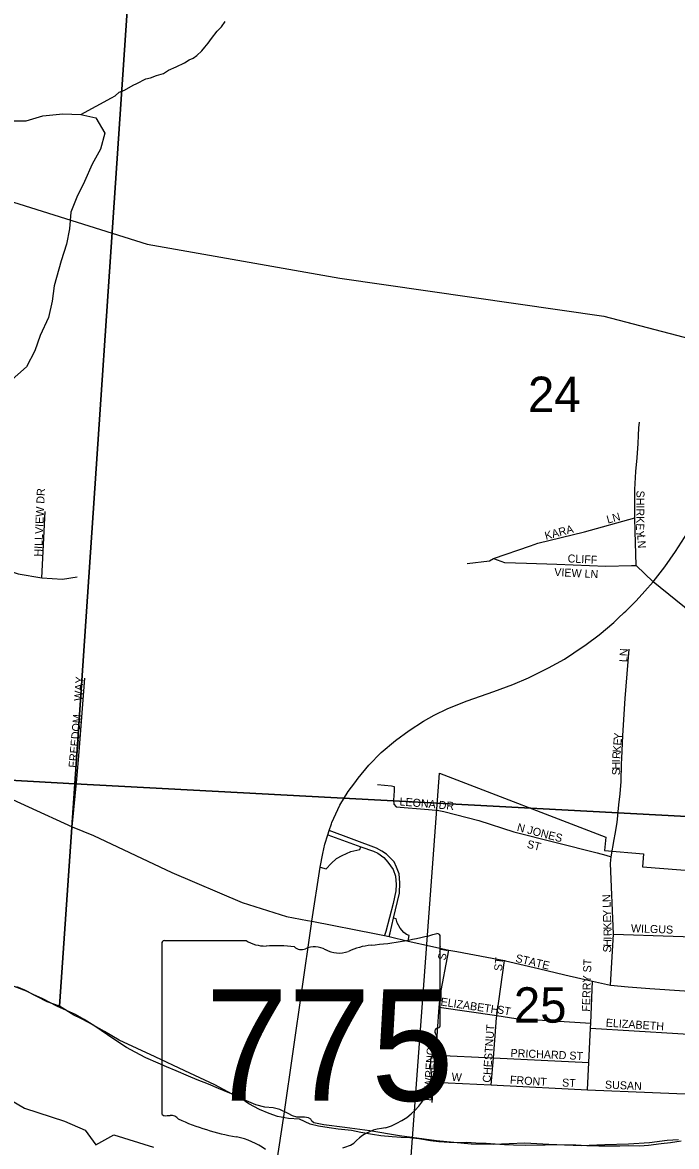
# Model space of a CAD drawing. Extents: x 0 to 34, y 0 to 22.
# Drawn here: x 7.778 to 8.552, y 16.434 to 17.764 of the extents above; entities that cross this region are included whole.
import ezdxf

# ---------------------------------------------------------------- set-up
doc = ezdxf.new("R2010")
doc.units = 0
for name, color, linetype in [('GM_P_State_Alignment', 7, 'Continuous'), ('GM_X_City_Street', 7, 'Continuous'), ('GM_X_City_Street_Text', 7, 'Continuous'), ('GM_X_Corporation', 7, 'Continuous'), ('GM_X_County', 7, 'Continuous'), ('GM_X_County_Road', 7, 'Continuous'), ('GM_X_Interchange_Ramps', 7, 'Continuous'), ('GM_X_Major_River', 7, 'Continuous'), ('GM_X_Minor_River', 7, 'Continuous'), ('GM_X_Section', 7, 'Continuous'), ('GM_X_Section_Text', 7, 'Continuous'), ('GM_X_State_Location', 7, 'Continuous'), ('GM_X_State_Route', 7, 'Continuous'), ('GM_X_State_Shield', 7, 'Continuous'), ('GM_X_Township', 7, 'Continuous'), ('GM_X_Township_ROW', 7, 'Continuous'), ('GM_X_Township_Subdivision', 7, 'Continuous'), ('GM_X_Township_Subdivision_Text', 7, 'Continuous'), ('SH_Data', 7, 'Continuous')]:
    doc.layers.add(name, color=color, linetype=linetype)

msp = doc.modelspace()

# ---------------------------------------------------------------- linework, layer by layer
at = {"layer": 'GM_P_State_Alignment'}
for points in [[(5.7539, 17.3702), (5.755, 17.3719), (5.7846, 17.4188), (6.0315, 17.5972), (6.2517, 17.7771), (6.3812, 17.906), (6.3923, 17.9142), (6.5211, 17.9881), (6.5265, 17.9911), (6.5405, 17.99), (6.6417, 17.9816), (6.6804, 17.9677), (6.7928, 17.9227), (6.8111, 17.9139), (6.95, 17.8445), (6.9564, 17.8413), (6.9734, 17.8302), (7.1338, 17.7232), (7.4175, 17.6454), (7.7316, 17.5623), (7.9253, 17.5014), (8.1533, 17.4614), (8.4655, 17.4165), (8.5004, 17.4073)], [(8.5004, 17.4073), (8.7912, 17.3314)]]:
    msp.add_lwpolyline(points, dxfattribs=at)
at = {"layer": 'GM_X_City_Street'}
for points in [[(8.2667, 16.8321), (8.2683, 16.832), (8.2762, 16.8306), (8.3175, 16.8198), (8.3592, 16.8063), (8.4575, 16.7816), (8.4679, 16.7786), (8.4744, 16.7767)], [(8.4734, 16.6248), (8.4768, 16.6854), (8.4735, 16.7691), (8.4744, 16.7767), (8.4777, 16.7974), (8.4788, 16.8038)], [(8.4768, 16.6854), (8.6181, 16.6806), (8.6813, 16.6766), (8.7568, 16.6712)], [(8.2627, 16.6708), (8.2823, 16.6665), (8.2915, 16.6648)], [(8.2713, 16.6069), (8.2716, 16.6105), (8.2823, 16.6665)], [(8.2915, 16.6648), (8.3481, 16.654), (8.3493, 16.6537)], [(8.3382, 16.5807), (8.3383, 16.5821), (8.3389, 16.589), (8.3481, 16.654)], [(8.3493, 16.6537), (8.3884, 16.6446), (8.4194, 16.6371), (8.4523, 16.6297), (8.4734, 16.6248), (8.4942, 16.6229), (8.5198, 16.6212), (8.6079, 16.6151), (8.6788, 16.6107), (8.7511, 16.605)], [(8.4463, 16.501), (8.4478, 16.5336), (8.4497, 16.574), (8.45, 16.5802), (8.4523, 16.6297)], [(8.2624, 16.486), (8.2642, 16.5104), (8.2666, 16.5421), (8.2708, 16.5988), (8.2713, 16.6069)], [(8.2708, 16.5988), (8.3389, 16.589), (8.3615, 16.5857), (8.45, 16.5802)], [(8.3321, 16.5069), (8.3348, 16.5389), (8.3382, 16.5807)], [(8.4497, 16.574), (8.6046, 16.5646), (8.6746, 16.5603), (8.7492, 16.5557)], [(8.2666, 16.5421), (8.3341, 16.5389), (8.3348, 16.5389), (8.4478, 16.5336)], [(8.2642, 16.5104), (8.3321, 16.5069), (8.3392, 16.5065), (8.3392, 16.5065)], [(8.3392, 16.5065), (8.4463, 16.501)], [(8.4463, 16.501), (8.6001, 16.4947)]]:
    msp.add_lwpolyline(points, dxfattribs=at)
at = {"layer": 'GM_X_Corporation'}
msp.add_lwpolyline([(8.236, 16.4015), (8.2709, 16.8756), (8.4678, 16.8002), (8.4665, 16.7841), (8.5125, 16.7805), (8.5113, 16.765), (8.6273, 16.756), (8.6258, 16.7367), (8.9074, 16.7147), (8.8957, 16.4847), (8.8556, 16.4772), (8.7669, 16.4493), (8.683, 16.4407), (8.6432, 16.4316), (8.5837, 16.4231), (8.5237, 16.4215), (8.501, 16.41), (8.4733, 16.3978), (8.4202, 16.4034), (8.4065, 16.411), (8.3439, 16.4128), (8.2972, 16.4195), (8.2722, 16.4039)], close=True, dxfattribs=at)
at = {"layer": 'GM_X_County'}
msp.add_lwpolyline([(7.7306, 16.5083), (7.78, 16.4795), (7.8274, 16.464), (7.8517, 16.4534), (7.8643, 16.4359), (7.8859, 16.4481), (7.9326, 16.4334)], dxfattribs=at)
at = {"layer": 'GM_X_County_Road'}
for points in [[(8.7724, 16.9734), (8.7004, 17.0073), (8.6711, 17.0201), (8.6214, 17.0364), (8.5939, 17.048), (8.5693, 17.0655), (8.5238, 17.102)], [(8.2117, 16.6826), (8.2339, 16.677)], [(8.2339, 16.677), (8.2627, 16.6708)]]:
    msp.add_lwpolyline(points, dxfattribs=at)
at = {"layer": 'GM_X_Interchange_Ramps'}
for points in [[(8.1388, 16.8027), (8.1432, 16.8014), (8.1782, 16.7888), (8.1929, 16.7835), (8.1982, 16.7812), (8.2051, 16.7759), (8.2101, 16.7705), (8.2164, 16.762), (8.2189, 16.7538), (8.22, 16.7441), (8.2193, 16.7366), (8.2164, 16.7216), (8.2076, 16.6885), (8.2062, 16.6836)], [(8.1299, 16.7646), (8.1368, 16.7626), (8.143, 16.7688), (8.1492, 16.7747), (8.156, 16.7785), (8.1662, 16.7832), (8.1768, 16.7853), (8.1782, 16.7888)], [(8.2339, 16.677), (8.2353, 16.6836), (8.2321, 16.6849), (8.2287, 16.6872), (8.2247, 16.6923), (8.221, 16.6987), (8.22, 16.7035), (8.2168, 16.7044)]]:
    msp.add_lwpolyline(points, dxfattribs=at)
at = {"layer": 'GM_X_Major_River'}
msp.add_lwpolyline([(8.5572, 16.4405), (8.5443, 16.4386), (8.5333, 16.4374), (8.5186, 16.4351), (8.508, 16.4347), (8.4951, 16.435), (8.4845, 16.4346), (8.4595, 16.4345), (8.4455, 16.4349), (8.4323, 16.4356), (8.419, 16.4356), (8.4073, 16.4359), (8.3963, 16.4355), (8.3725, 16.4354), (8.3585, 16.4358), (8.3482, 16.4361), (8.3369, 16.4369), (8.3263, 16.4376), (8.3142, 16.4379), (8.3032, 16.4387), (8.2926, 16.4386), (8.2824, 16.439), (8.2702, 16.4397), (8.2604, 16.4408), (8.2468, 16.4431), (8.2358, 16.4442), (8.2256, 16.4449), (8.215, 16.4457), (8.2017, 16.4468), (8.1919, 16.4483), (8.1779, 16.4505), (8.1669, 16.4531), (8.151, 16.4546), (8.1404, 16.4561), (8.1279, 16.458), (8.118, 16.4606), (8.1055, 16.4666), (8.0926, 16.4674), (8.0794, 16.4696), (8.0695, 16.473), (8.0582, 16.4779), (8.0456, 16.4847), (8.0324, 16.4938), (8.021, 16.498), (8.0096, 16.5029), (7.9979, 16.5078), (7.9842, 16.5131), (7.974, 16.5172), (7.9596, 16.5236), (7.9482, 16.5285), (7.938, 16.5327), (7.9236, 16.5391), (7.9111, 16.5459), (7.9008, 16.5512), (7.8891, 16.5588), (7.8781, 16.5664), (7.8633, 16.5766), (7.8508, 16.5845), (7.8405, 16.5902), (7.8296, 16.5951), (7.8182, 16.6), (7.8019, 16.6087), (7.7901, 16.614), (7.7803, 16.6189), (7.7708, 16.6231)], dxfattribs=at)
at = {"layer": 'GM_X_Minor_River'}
for points in [[(7.8465, 17.6549), (7.8828, 17.6749), (7.8874, 17.6771), (7.8921, 17.6816), (7.8982, 17.6838), (7.9085, 17.6897), (7.9131, 17.6915), (7.9234, 17.697), (7.9291, 17.6985), (7.9363, 17.701), (7.9443, 17.7035), (7.9505, 17.7076), (7.9596, 17.7112), (7.9695, 17.716), (7.9749, 17.7197), (7.9795, 17.7215), (7.9841, 17.7249), (7.9899, 17.7305), (7.9934, 17.7346), (7.9972, 17.7395), (8.0011, 17.7447), (8.0081, 17.7537), (8.0131, 17.7586), (8.0174, 17.765)], [(7.7624, 17.6474), (7.7821, 17.6474), (7.8018, 17.6534), (7.8253, 17.6557), (7.8465, 17.6549), (7.8646, 17.6511), (7.8752, 17.6329), (7.8699, 17.6139), (7.86, 17.5964), (7.8509, 17.5759), (7.8418, 17.557), (7.835, 17.5395), (7.8334, 17.5198), (7.8296, 17.5015), (7.8235, 17.4818), (7.8151, 17.4522), (7.8128, 17.434), (7.8083, 17.415), (7.7984, 17.3937), (7.7923, 17.3755), (7.7825, 17.3565), (7.762, 17.3383)]]:
    msp.add_lwpolyline(points, dxfattribs=at)
at = {"layer": 'GM_X_Section'}
for points in [[(6.8533, 17.9287), (7.9078, 17.8715), (7.8396, 16.8632), (6.7904, 16.9223)], [(7.9078, 17.8715), (8.9857, 17.8095), (8.9637, 17.4779), (8.9185, 16.8056), (7.8396, 16.8632)]]:
    msp.add_lwpolyline(points, close=True, dxfattribs=at)
for points in [[(6.7904, 16.9223), (7.8396, 16.8632), (7.8216, 16.6003), (7.8068, 16.6052), (7.7822, 16.618), (7.7594, 16.6267)], [(8.5541, 16.442), (8.5405, 16.4413), (8.5196, 16.4386), (8.4946, 16.4367), (8.4666, 16.4359), (8.4386, 16.4348), (8.4003, 16.4366), (8.3722, 16.4381), (8.3351, 16.4366), (8.3086, 16.4369), (8.2677, 16.4407), (8.2237, 16.4467), (8.1888, 16.4528), (8.1589, 16.4565), (8.1343, 16.4599), (8.1225, 16.4622), (8.1199, 16.4641), (8.1187, 16.4663), (8.1161, 16.4682), (8.1115, 16.469), (8.1024, 16.469), (8.0971, 16.4705), (8.0922, 16.4732), (8.082, 16.4777), (8.0744, 16.48), (8.0645, 16.4807), (8.0539, 16.4833), (8.0308, 16.4932), (8.0054, 16.5072), (7.9698, 16.5238), (7.9345, 16.5401), (7.8921, 16.5601), (7.8746, 16.57), (7.8557, 16.581), (7.8466, 16.5855), (7.8383, 16.5893), (7.8216, 16.6003), (7.8396, 16.8632), (8.9185, 16.8056)]]:
    msp.add_lwpolyline(points, dxfattribs=at)
at = {"layer": 'GM_X_State_Route'}
for points in [[(8.5238, 17.102), (8.5377, 17.1197), (8.5503, 17.1379), (8.561, 17.1546), (8.6186, 17.2417), (8.6311, 17.2603), (8.6396, 17.272), (8.6508, 17.2842), (8.6646, 17.2964), (8.679, 17.3061), (8.6962, 17.3156), (8.7118, 17.3223), (8.7269, 17.3267), (8.7429, 17.3294), (8.768, 17.331), (8.7912, 17.3314)], [(8.4898, 17.0658), (8.4917, 17.0676), (8.5039, 17.0797), (8.5142, 17.0909), (8.5238, 17.102)], [(8.4825, 17.0591), (8.4898, 17.0658)], [(8.1438, 16.8173), (8.1531, 16.838), (8.1632, 16.8539), (8.1709, 16.8645), (8.1747, 16.8697), (8.1876, 16.8851), (8.2019, 16.9002), (8.2191, 16.9145), (8.2352, 16.9263), (8.2523, 16.9374), (8.2646, 16.9443), (8.281, 16.9523), (8.3037, 16.9613), (8.3195, 16.9669), (8.3354, 16.9725), (8.3579, 16.9807), (8.3766, 16.9886), (8.4, 17.0005), (8.4189, 17.0108), (8.4299, 17.0182), (8.4446, 17.0281), (8.46, 17.0396), (8.4772, 17.0542), (8.4825, 17.0591)], [(7.1864, 16.9474), (7.2045, 16.9563), (7.2367, 16.9724), (7.2728, 16.9836), (7.3418, 16.9926), (7.3896, 16.9926), (7.4398, 16.9834), (7.4853, 16.9717), (7.5264, 16.9569), (7.6294, 16.9068), (7.8363, 16.8124), (7.8617, 16.8021), (7.9545, 16.7583), (8.0376, 16.7228), (8.0899, 16.7064), (8.1147, 16.7016)], [(8.1405, 16.8079), (8.1432, 16.8159), (8.1438, 16.8173)], [(8.1191, 16.6946), (8.12, 16.7005), (8.1299, 16.7646), (8.133, 16.7807), (8.1356, 16.7918), (8.1388, 16.8027), (8.1405, 16.8079)], [(8.2117, 16.6826), (8.2127, 16.687), (8.2168, 16.7044), (8.2237, 16.7337), (8.2243, 16.7462), (8.2233, 16.7568), (8.2204, 16.7647), (8.2174, 16.7708), (8.2133, 16.7751), (8.2082, 16.78), (8.2029, 16.7835), (8.1964, 16.7869), (8.1405, 16.8079)], [(8.0701, 16.3583), (8.0873, 16.4725), (8.1191, 16.6946)], [(8.1147, 16.7016), (8.12, 16.7005), (8.1961, 16.6857), (8.2062, 16.6836), (8.2117, 16.6826)]]:
    msp.add_lwpolyline(points, dxfattribs=at)
at = {"layer": 'GM_X_State_Shield'}
for p, q in [((8.0422, 16.6776), (7.9456, 16.6776)), ((8.272, 16.5779), (8.272, 16.6826)), ((7.9424, 16.6742), (7.9424, 16.4741)), ((8.2719, 16.5779), (8.272, 16.5779))]:
    msp.add_line(p, q, dxfattribs=at)
for centre, major_axis, start_param, end_param in [((7.9462, 16.6746), (0.00382, 0), 1.712693, 3.28349), ((8.0651, 16.7009), (0.037, 0), 4.042523, 4.731795), ((8.1546, 16.9505), (0.3495, 0), 4.814394, 5.042369), ((8.2683, 16.683), (0.00367, 0), 6.141152, 7.989035), ((8.0774, 16.5653), (0.133, 0), 1.404758, 1.657858), ((8.1076, 16.6757), (0.0107, 0), 3.836095, 5.185415), ((8.1233, 16.6525), (0.0222, 0), 0.950623, 2.079405), ((8.152, 16.6843), (0.0267, 0), 4.081561, 5.145723), ((8.1992, 16.6165), (0.0703, 0), 1.699011, 2.107814), ((8.2711, 16.5702), (0.00568, 0), 1.883978, 3.671073), ((8.2681, 16.5775), (0.00393, 0), 5.05454, 6.418171), ((8.235, 16.557), (0.0341, 0), 5.934695, 6.695948), ((8.2851, 16.5341), (0.0248, 0), 2.387724, 3.262537), ((8.1741, 16.5208), (0.0874, 0), 5.101752, 6.440018), ((7.9462, 16.4736), (0.00385, 0), 3.00124, 4.508301), ((7.9468, 16.4941), (0.0294, 0), 4.665946, 4.897461), ((7.9528, 16.4625), (0.0106, 0), 0.519207, 1.627899), ((8.0866, 16.6423), (0.2524, 0), 4.195997, 4.488961), ((8.211, 16.4179), (0.0479, 0), 1.647645, 2.488434), ((8.0114, 16.3842), (0.079, 0), 0.823519, 1.323587), ((8.1503, 16.4547), (0.0282, 0), 4.937069, 5.64225)]:
    msp.add_ellipse(centre, major_axis=major_axis, ratio=0.8, start_param=start_param, end_param=end_param, dxfattribs=at)
at = {"layer": 'GM_X_Township'}
msp.add_lwpolyline([(7.7306, 16.5083), (7.78, 16.4795), (7.8274, 16.464), (7.8517, 16.4534), (7.8643, 16.4359), (7.8859, 16.4481), (7.9326, 16.4334)], dxfattribs=at)
at = {"layer": 'GM_X_Township_ROW'}
for points in [[(8.3038, 17.124), (8.3304, 17.127), (8.3349, 17.1299), (8.3789, 17.1449)], [(8.3349, 17.1299), (8.3479, 17.1249), (8.3739, 17.1242)]]:
    msp.add_lwpolyline(points, dxfattribs=at)
at = {"layer": 'GM_X_Township_Subdivision'}
for points in [[(8.5037, 17.1215), (8.5027, 17.1619), (8.5022, 17.178), (8.5024, 17.2112), (8.5036, 17.2326), (8.5049, 17.2489), (8.5063, 17.2658), (8.5067, 17.2751), (8.5071, 17.2845), (8.5076, 17.2911)], [(7.8004, 17.107), (7.8046, 17.1855)], [(8.3789, 17.1449), (8.3873, 17.1477), (8.4427, 17.1614), (8.5022, 17.178)], [(7.6294, 16.9068), (7.6434, 16.9515), (7.6461, 16.9633), (7.6446, 16.9762), (7.6404, 16.9879), (7.6287, 17.011), (7.6142, 17.0467), (7.6051, 17.0747), (7.5979, 17.0937), (7.5995, 17.1062), (7.6032, 17.1157), (7.607, 17.1278), (7.6165, 17.1392), (7.6302, 17.1464), (7.6457, 17.1502), (7.6639, 17.1506), (7.6874, 17.1438), (7.709, 17.1358), (7.7492, 17.1195), (7.7724, 17.1115), (7.8004, 17.107), (7.8251, 17.1051), (7.8425, 17.1081)], [(8.3739, 17.1242), (8.4098, 17.1231), (8.4679, 17.1205), (8.4982, 17.1214), (8.5037, 17.1215)], [(8.5238, 17.102), (8.5037, 17.1215)], [(8.4867, 16.8931), (8.4879, 16.9205), (8.4909, 16.964), (8.4956, 17.0225)], [(7.8363, 16.8124), (7.8419, 16.8688), (7.8449, 16.901), (7.8515, 16.988)], [(8.4788, 16.8038), (8.4812, 16.8176), (8.4832, 16.8382), (8.4847, 16.8514), (8.4859, 16.8661), (8.4865, 16.887), (8.4867, 16.8931)], [(8.1976, 16.8625), (8.2143, 16.8609), (8.2174, 16.8599), (8.2173, 16.8548), (8.2165, 16.8439), (8.2171, 16.8391), (8.2198, 16.8358), (8.2581, 16.8328), (8.2667, 16.8321)]]:
    msp.add_lwpolyline(points, dxfattribs=at)
at = {"layer": 'SH_Data'}
msp.add_lwpolyline([(7.7316, 17.5623), (7.9253, 17.5014), (8.1533, 17.4614), (8.4655, 17.4165), (8.7912, 17.3314), (8.8137, 17.3309), (8.8372, 17.3319), (8.857, 17.3337)], dxfattribs=at)

# ---------------------------------------------------------------- texts
at = {"layer": 'GM_X_City_Street_Text'}
for s, rotation, p in [('N JONES', 345.4658, (8.3621, 16.8077)), ('ST', 345.9622, (8.3739, 16.7877)), ('N', 91.9675, (8.4735, 16.7234)), ('L', 91.9675, (8.4737, 16.7167)), ('Y', 91.9922, (8.4741, 16.7059)), ('E', 91.9821, (8.4743, 16.6992)), ('K', 91.9122, (8.4746, 16.6909)), ('R', 90.5529, (8.4747, 16.6831)), ('WILGUS', 357.8788, (8.4975, 16.6877)), ('H', 87.8571, (8.4743, 16.6702)), ('I', 88.1898, (8.4746, 16.6786)), ('ST', 79.3729, (8.2782, 16.6538)), ('S', 87.8412, (8.474, 16.6635)), ('ST', 82.8789, (8.3448, 16.6412)), ('STATE', 346.6075, (8.3604, 16.6527)), ('FERRY ST', 88.1534, (8.449, 16.5935)), ('ELIZABETH', 351.6563, (8.2719, 16.601)), ('ST', 349.382, (8.3386, 16.5919)), ('ELIZABETH', 356.2359, (8.4676, 16.576)), ('CHESTNUT', 86.0809, (8.3315, 16.5094)), ('LAWRENCE', 86.2836, (8.2615, 16.4877)), ('PRICHARD ST', 357.4552, (8.355, 16.5402)), ('W', 355.6018, (8.2851, 16.5119)), ('FRONT', 356.2687, (8.3542, 16.5085)), ('ST', 356.4237, (8.4159, 16.5052)), ('SUSAN', 357.5105, (8.4667, 16.5027))]:
    msp.add_text(s, height=0.00947, rotation=rotation, dxfattribs=at).set_placement(p)
at = {"layer": 'GM_X_Section_Text'}
for s, p in [('24', (8.3758, 17.303)), ('25', (8.3591, 16.5806))]:
    msp.add_text(s, height=0.04186, rotation=0, dxfattribs=at).set_placement(p)
at = {"layer": 'GM_X_State_Location'}
for s in ['s', 'r']:
    msp.add_text(s, height=0.000189, dxfattribs=at).set_placement((8.1035, 16.5608))
msp.add_text('775', height=0.000189, rotation=0, dxfattribs=at).set_placement((8.0366, 16.5471))
at = {"layer": 'GM_X_State_Shield'}
msp.add_text('775', height=0.13184, dxfattribs=at).set_placement((7.9939, 16.4882))
at = {"layer": 'GM_X_Township_Subdivision_Text'}
for s, rotation, p in [('HILLVIEW DR', 87.4845, (7.8007, 17.1318)), ('SHIRKEY', 269.4789, (8.5042, 17.2101)), ('LN', 15.5232, (8.4703, 17.1709)), ('KARA', 14.7446, (8.397, 17.1518)), ('LN', 273.0111, (8.5051, 17.1577)), ('CLIFF', 356.9866, (8.4225, 17.1252)), ('VIEW LN', 357.0389, (8.4067, 17.1091)), ('LN', 86.9774, (8.4932, 17.0069)), ('WAY', 86.4256, (7.8482, 16.961)), ('FREEDOM', 84.8838, (7.8415, 16.8819)), ('E', 85.2409, (8.4861, 16.9082)), ('Y', 85.2558, (8.4866, 16.9148)), ('K', 85.2736, (8.4854, 16.8999)), ('I', 88.9945, (8.4848, 16.8884)), ('H', 89.9344, (8.4848, 16.8801)), ('R', 86.5007, (8.4849, 16.8924)), ('S', 89.9454, (8.4848, 16.8734)), ('LEONA DR', 355.1008, (8.2235, 16.8377))]:
    msp.add_text(s, height=0.00947, rotation=rotation, dxfattribs=at).set_placement(p)

doc.saveas('drawing.dxf')
